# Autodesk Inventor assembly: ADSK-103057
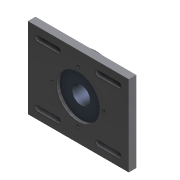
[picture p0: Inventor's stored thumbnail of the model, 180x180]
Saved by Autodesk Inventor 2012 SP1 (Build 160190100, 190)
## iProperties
Shininess: 0.0
Created: 2000-11
Part Number: ADSK-103057
Document SubType Name: Assembly
Stock Number: ADSK-103057
Density: 0.0
Volumn: 0.0
Area: 0.0
PropertySet Name: Model Information
Control State: 0
Master: False
Checked Out: False
Author: gao
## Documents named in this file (3)
- D:\AOTC\Autodesk Inventor 2012 Essential for New Users\Autodesk Inventor 2012 Essentials - Project Files\Learning\Workspace\Sub-Assemblies\ADSK-103057.iam
- D:\AOTC\Autodesk Inventor 2012 Essential for New Users\Autodesk Inventor 2012 Essentials - Project Files\Learning\Workspace\Parts\ADSK-103436.ipt
- D:\AOTC\Autodesk Inventor 2012 Essential for New Users\Autodesk Inventor 2012 Essentials - Project Files\Learning\Workspace\Parts\ADSK-103439.ipt
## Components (2 placed, 2 different names)
1. ADSK-103439:1 — Insert:1
2. ADSK-103436:1 — Insert:1
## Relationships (1: Insert 1)
- Insert:1: ADSK-103439:1 ↔ ADSK-103436:1
